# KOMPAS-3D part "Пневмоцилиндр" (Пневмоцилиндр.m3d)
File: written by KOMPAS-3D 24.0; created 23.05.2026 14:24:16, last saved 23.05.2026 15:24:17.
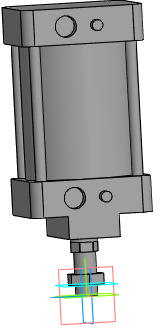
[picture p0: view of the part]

Document properties: Автор: R2D2; Полное имя файла: E:\Работа\Зайцев\GVKR1331E-1W-Fb-2P Задвижка шиберная DN.ru Ду50-300 Ру16-10-6\исходные материалы\Пневмоцилиндр.m3d

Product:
- Part/product: Пневмоцилиндр
    Масса: 15.361581

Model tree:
1. Эскиз:1
2. Элемент выдавливания:1
3. Смещенная плоскость:1
4. Эскиз:2
5. Элемент выдавливания:2
6. Эскиз:3  (with: Грань.Элемент выдавливания:1)
7. Элемент выдавливания:3
8. Эскиз:4  (with: Грань.Элемент выдавливания:3)
9. Элемент выдавливания:4  (with: Грань.Элемент выдавливания:3)
     Расстояние 2 = 9; Смещение 2 = 5
10. Эскиз:5  (with: Грань.Элемент выдавливания:3)
11. Элемент выдавливания:5
12. Эскиз:6  (with: Грань.Элемент выдавливания:5)
13. Элемент выдавливания:6
14. Эскиз:7  (with: Грань.Элемент выдавливания:6)
15. Элемент выдавливания:7
16. Эскиз:8  (with: Грань.Элемент выдавливания:7, Ребро.Элемент выдавливания:6)
17. Элемент выдавливания:8
18. Эскиз:9  (with: Грань.Элемент выдавливания:6, Вершина.Элемент выдавливания:8)
19. Элемент выдавливания:9  (with: Грань.Элемент выдавливания:8)
     Расстояние 1 = 123
20. Массив по концентрической сетке:1  (with: Элемент выдавливания:9, Эскиз:9)  (4 pattern instances)
     Шаг 2 = 360
21. Скругление:1  (with: Ребро.Элемент выдавливания:6, Ребро.Элемент выдавливания:8)
     Радиус = 10
22. Эскиз:10  (with: Грань.Элемент выдавливания:5, Ребро.Элемент выдавливания:6, Ребро.Элемент выдавливания:8)
23. Элемент выдавливания:10
24. Эскиз:11  (with: Грань.Элемент выдавливания:5, Ребро.Элемент выдавливания:10)
25. Элемент выдавливания:11

Expressions: k/2; c-2*g+x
